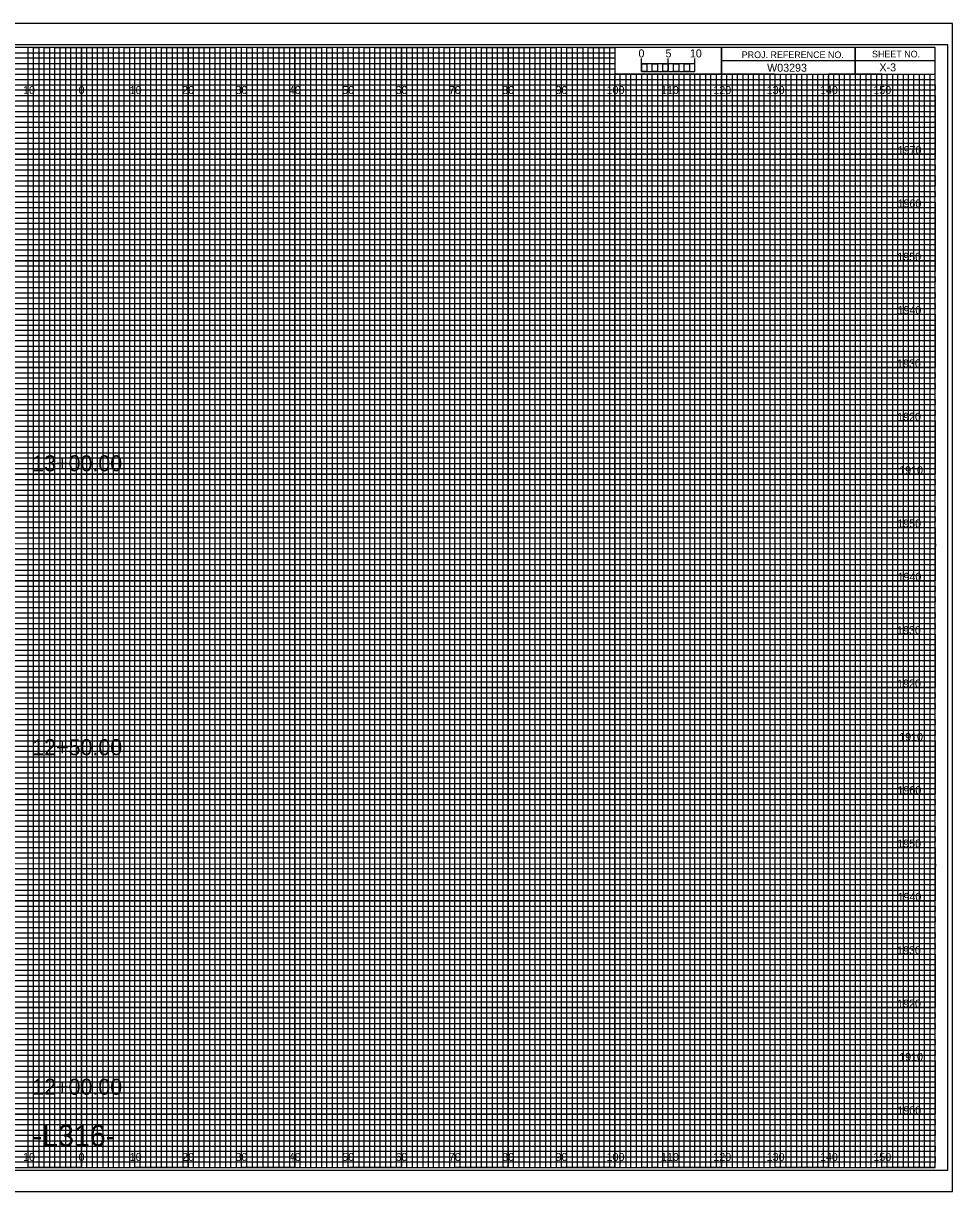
# Model space of a CAD drawing. Extents: x -13 to 323, y 215 to 434.
# Drawn here: x 149.1 to 323.3, y 215.5 to 434.5 of the extents above; entities that cross this region are included whole.
import ezdxf

# ---------------------------------------------------------------- set-up
doc = ezdxf.new("R2010")
doc.units = 0
for name, color, linetype in [('Exist Cross Section Cell', 7, 'Continuous'), ('Exist XS Center Line Elevation Label', 7, 'Continuous'), ('Exist XS Ground Line', 7, 'Continuous'), ('Prop CMT Concrete Ditch', 7, 'Continuous'), ('Prop XS Ditch Standard Text', 7, 'Continuous'), ('Prop XS Finish Grade Earthwork', 7, 'Continuous'), ('Prop XS Guardrail', 7, 'Continuous'), ('Prop XS Retaining Wall', 7, 'Continuous'), ('Prop XS SE Text', 7, 'Continuous'), ('Prop XS Side Slope Text', 7, 'Continuous'), ('Prop XS Subgrade Earthwork', 7, 'Continuous'), ('Prop XSC Text', 7, 'Continuous'), ('Scratch_Level_0', 7, 'Continuous'), ('Scratch_Level_5', 7, 'Continuous'), ('Scratch_Level_6', 7, 'Continuous'), ('Typical Guardrail CELL', 7, 'Continuous')]:
    doc.layers.add(name, color=color, linetype=linetype)

msp = doc.modelspace()

# ---------------------------------------------------------------- linework, layer by layer
at = {"layer": 'Exist Cross Section Cell'}
for points in [[(145, 220), (155, 220), (155, 430), (165, 430), (165, 220), (175, 220), (175, 430), (185, 430), (185, 220), (195, 220), (195, 430), (205, 430), (205, 220), (215, 220), (215, 430), (225, 430), (225, 220), (235, 220), (235, 430), (245, 430), (245, 220), (255, 220), (255, 430), (259.93, 430), (260, 430), (260, 425), (264.99, 425), (264.99, 220), (275, 220), (275, 425), (285, 425), (285, 220), (295, 220), (295, 425), (305, 425), (305, 220), (315, 220), (315, 425)], [(0, 425), (275, 425)], [(0, 405), (320, 405), (320, 415), (0, 415)], [(0, 385), (320, 385), (320, 395), (0, 395)], [(0, 365), (320, 365), (320, 375), (0, 375)], [(0, 345), (320, 345), (320, 355), (0, 355)], [(0, 325), (320, 325), (320, 335), (0, 335)], [(0, 305), (320, 305), (320, 315), (0, 315)], [(0, 285), (320, 285), (320, 295), (0, 295)], [(0, 265), (320, 265), (320, 275), (0, 275)], [(0, 245), (320, 245), (320, 255), (0, 255)], [(0, 225), (320, 225), (320, 235), (0, 235)]]:
    msp.add_lwpolyline(points, dxfattribs=at)
at = {"layer": 'Exist XS Center Line Elevation Label'}
for p, q in [((150, 430), (140, 430)), ((150, 220), (150, 430)), ((170, 430), (160, 430)), ((160, 430), (160, 220)), ((170, 220), (170, 430)), ((190, 430), (180, 430)), ((180, 430), (180, 220)), ((190, 220), (190, 430)), ((210, 430), (200, 430)), ((200, 430), (200, 220)), ((210, 220), (210, 430)), ((230, 430), (220, 430)), ((220, 430), (220, 220)), ((230, 220), (230, 430)), ((250, 430), (240, 430)), ((240, 430), (240, 220)), ((250, 220), (250, 430)), ((260, 430), (260, 220)), ((270, 220), (270, 425)), ((290, 425), (280, 425)), ((280, 425), (280, 220)), ((290, 220), (290, 425)), ((310, 425), (300, 425)), ((300, 425), (300, 220)), ((310, 220), (310, 425)), ((160, 220), (150, 220)), ((180, 220), (170, 220)), ((200, 220), (190, 220)), ((220, 220), (210, 220)), ((240, 220), (230, 220)), ((260, 220), (250, 220)), ((280, 220), (270, 220)), ((300, 220), (290, 220)), ((320, 220), (310, 220)), ((320, 220), (320, 220))]:
    msp.add_line(p, q, dxfattribs=at)
for points in [[(0, 420), (320, 420), (320, 410), (0, 410)], [(0, 400), (320, 400), (320, 390), (0, 390)], [(0, 380), (320, 380), (320, 370), (0, 370)], [(0, 360), (320, 360), (320, 350), (0, 350)], [(0, 340), (320, 340), (320, 330), (0, 330)], [(0, 320), (320, 320), (320, 310), (0, 310)], [(0, 300), (320, 300), (320, 290), (0, 290)], [(0, 280), (320, 280), (320, 270), (0, 270)], [(0, 260), (320, 260), (320, 250), (0, 250)], [(0, 240), (320, 240), (320, 230), (0, 230)]]:
    msp.add_lwpolyline(points, dxfattribs=at)
at = {"layer": 'Prop CMT Concrete Ditch'}
for p, q in [((265, 425.49), (265, 427.9)), ((265, 426.9), (265, 427.9)), ((270, 425.49), (270, 427.9)), ((275, 425.49), (275, 427.9)), ((275, 426.9), (275, 427.9))]:
    msp.add_line(p, q, dxfattribs=at)
for points in [[(275, 426.9), (265, 426.9), (265, 425.49), (275, 425.49)], [(265, 426.9), (266, 426.9), (266, 425.49), (265, 425.49)], [(267, 426.9), (268, 426.9), (268, 425.49), (267, 425.49)], [(269, 426.9), (270, 426.9), (270, 425.49), (269, 425.49)], [(271, 426.9), (272, 426.9), (272, 425.49), (271, 425.49)], [(273, 426.9), (274, 426.9), (274, 425.49), (273, 425.49)]]:
    msp.add_lwpolyline(points, close=True, dxfattribs=at)
at = {"layer": 'Prop XS Finish Grade Earthwork'}
for p, q in [((323.3, 434.5), (-13.4, 434.5)), ((-13.4, 215.5), (323.3, 215.5))]:
    msp.add_line(p, q, dxfattribs=at)
at = {"layer": 'Prop XS Retaining Wall'}
for p, q in [((267, 425), (266.01, 425)), ((266.01, 425), (266.01, 220)), ((267, 220), (267, 425)), ((269, 425), (268, 425)), ((268, 425), (268, 220)), ((269, 220), (269, 425)), ((266.01, 220), (265, 220)), ((268, 220), (267, 220))]:
    msp.add_line(p, q, dxfattribs=at)
for points in [[(150, 220), (151, 220), (151, 430), (152, 430), (152, 220)], [(152, 220), (153, 220), (153, 430), (154, 430), (154, 220)], [(155, 220), (156, 220), (156, 430), (157, 430), (157, 220)], [(157, 220), (158, 220), (158, 430), (159, 430), (159, 220)], [(160, 220), (161, 220), (161, 430), (162, 430), (162, 220)], [(162, 220), (163, 220), (163, 430), (164, 430), (164, 220)], [(165, 220), (166, 220), (166, 430), (167, 430), (167, 220)], [(167, 220), (168, 220), (168, 430), (169, 430), (169, 220)], [(170, 220), (171, 220), (171, 430), (172, 430), (172, 220)], [(172, 220), (173, 220), (173, 430), (174, 430), (174, 220)], [(175, 220), (176, 220), (176, 430), (177, 430), (177, 220)], [(177, 220), (178, 220), (178, 430), (179, 430), (179, 220)], [(180, 220), (181, 220), (181, 430), (182, 430), (182, 220)], [(182, 220), (183, 220), (183, 430), (184, 430), (184, 220)], [(185, 220), (186, 220), (186, 430), (187, 430), (187, 220)], [(187, 220), (188, 220), (188, 430), (189, 430), (189, 220)], [(190, 220), (191, 220), (191, 430), (192, 430), (192, 220)], [(192, 220), (193, 220), (193, 430), (194, 430), (194, 220)], [(195, 220), (196, 220), (196, 430), (197, 430), (197, 220)], [(197, 220), (198, 220), (198, 430), (199, 430), (199, 220)], [(200, 220), (201, 220), (201, 430), (202, 430), (202, 220)], [(202, 220), (203, 220), (203, 430), (204, 430), (204, 220)], [(205, 220), (206, 220), (206, 430), (207, 430), (207, 220)], [(207, 220), (208, 220), (208, 430), (209, 430), (209, 220)], [(210, 220), (211, 220), (211, 430), (212, 430), (212, 220)], [(212, 220), (213, 220), (213, 430), (214, 430), (214, 220)], [(215, 220), (216, 220), (216, 430), (217, 430), (217, 220)], [(217, 220), (218, 220), (218, 430), (219, 430), (219, 220)], [(220, 220), (221, 220), (221, 430), (222, 430), (222, 220)], [(222, 220), (223, 220), (223, 430), (224, 430), (224, 220)], [(225, 220), (226, 220), (226, 430), (227, 430), (227, 220)], [(227, 220), (228, 220), (228, 430), (229, 430), (229, 220)], [(230, 220), (231, 220), (231, 430), (232, 430), (232, 220)], [(232, 220), (233, 220), (233, 430), (234, 430), (234, 220)], [(235, 220), (236, 220), (236, 430), (237, 430), (237, 220)], [(237, 220), (238, 220), (238, 430), (239, 430), (239, 220)], [(240, 220), (241, 220), (241, 430), (242, 430), (242, 220)], [(242, 220), (243, 220), (243, 430), (244, 430), (244, 220)], [(245, 220), (246, 220), (246, 430), (247, 430), (247, 220)], [(247, 220), (248, 220), (248, 430), (249, 430), (249, 220)], [(250, 220), (251, 220), (251, 430), (252, 430), (252, 220)], [(252, 220), (253, 220), (253, 430), (254, 430), (254, 220)], [(255, 220), (256, 220), (256, 430), (257, 430), (257, 220)], [(257, 220), (258, 220), (258, 430), (259, 430), (259, 220)], [(260, 220), (261, 220), (261, 425), (262.02, 425), (262.02, 220)], [(262, 220), (263, 220), (263, 425), (263.99, 425), (263.99, 220)], [(270, 220), (270.98, 220), (270.98, 425), (272, 425), (272, 220)], [(272, 220), (273, 220), (273, 425), (274.05, 425), (274.05, 220)], [(275, 220), (276, 220), (276, 425), (277, 425), (277, 220)], [(277, 220), (278, 220), (278, 425), (279, 425), (279, 220)], [(280, 220), (281, 220), (281, 425), (282, 425), (282, 220)], [(282, 220), (283, 220), (283, 425), (284, 425), (284, 220)], [(285, 220), (286, 220), (286, 425), (287, 425), (287, 220)], [(287, 220), (288, 220), (288, 425), (289, 425), (289, 220)], [(290, 220), (291, 220), (291, 425), (292, 425), (292, 220)], [(292, 220), (293, 220), (293, 425), (294, 425), (294, 220)], [(295, 220), (296, 220), (296, 425), (297, 425), (297, 220)], [(297, 220), (298, 220), (298, 425), (299, 425), (299, 220)], [(300, 220), (301, 220), (301, 425), (302, 425), (302, 220)], [(302, 220), (303, 220), (303, 425), (304, 425), (304, 220)], [(305, 220), (306, 220), (306, 425), (307, 425), (307, 220)], [(307, 220), (308, 220), (308, 425), (309, 425), (309, 220)], [(310, 220), (311, 220), (311, 425), (312, 425), (312, 220)], [(312, 220), (313, 220), (313, 425), (314, 425), (314, 220)], [(315, 220), (316, 220), (316, 425), (317, 425), (317, 220)], [(317, 220), (318, 220), (318, 425), (319, 425), (319, 220)]]:
    msp.add_lwpolyline(points, dxfattribs=at)
at = {"layer": 'Prop XSC Text'}
for p, q in [((150, 220), (150, 430)), ((160, 220), (160, 430)), ((170, 220), (170, 430)), ((180, 220), (180, 430)), ((190, 220), (190, 430)), ((200, 220), (200, 430)), ((210, 220), (210, 430)), ((220, 220), (220, 430)), ((230, 220), (230, 430)), ((240, 220), (240, 430)), ((250, 220), (250, 430)), ((260, 220), (260, 424.69)), ((270, 220), (270, 424.69)), ((280, 220), (280, 424.69)), ((290, 220), (290, 424.69)), ((300, 220), (300, 424.69)), ((310, 220), (310, 424.69)), ((0, 420), (320, 420)), ((0, 410), (320, 410)), ((0, 400), (320, 400)), ((0, 390), (320, 390)), ((0, 380), (320, 380)), ((0, 370), (320, 370)), ((0, 360), (320, 360)), ((0, 350), (320, 350)), ((0, 340), (320, 340)), ((0, 330), (320, 330)), ((0, 320), (320, 320)), ((0, 310), (320, 310)), ((0, 300), (320, 300)), ((0, 290), (320, 290)), ((0, 280), (320, 280)), ((0, 270), (320, 270)), ((0, 260), (320, 260)), ((0, 250), (320, 250)), ((0, 240), (320, 240)), ((0, 230), (320, 230))]:
    msp.add_line(p, q, dxfattribs=at)
at = {"layer": 'Scratch_Level_0'}
msp.add_lwpolyline([(-10.8, 219.5), (322.4, 219.5), (322.4, 430.5), (-10.8, 430.5)], close=True, dxfattribs=at)
at = {"layer": 'Scratch_Level_5'}
for p, q in [((0, 429), (260, 429)), ((260, 427.98), (0, 427.98)), ((260, 429), (260, 427.98)), ((0, 427), (260, 427)), ((260, 425.89), (0, 425.89)), ((260, 427), (260, 425.89)), ((0, 424), (320, 424))]:
    msp.add_line(p, q, dxfattribs=at)
for points in [[(0, 423), (270, 423), (320, 423), (320, 422), (0, 422)], [(0, 421), (320, 421), (320, 419), (0, 419)], [(0, 418), (320, 418), (320, 417), (0, 416.98)], [(0, 416), (320, 416), (320, 414), (0, 414)], [(0, 413), (320, 413), (320, 412), (0, 412)], [(0, 411), (320, 411), (320, 409), (0, 409)], [(0, 408), (320, 408), (320, 407), (0, 407)], [(0, 406), (320, 406), (320, 404), (0, 404)], [(0, 403), (320, 403), (320, 402), (0, 402)], [(0, 401), (320, 401), (320, 399), (0, 399)], [(0, 398), (320, 398), (320, 397), (0, 397)], [(0, 396), (320, 396), (320, 393.95), (320, 393), (320, 392), (0, 392)], [(0, 394), (320, 394), (320, 393), (0, 393)], [(0, 391), (320, 391), (320, 389), (0, 389.03)], [(0, 389.03), (320, 389), (320, 388), (0, 388)], [(0, 387), (320, 387), (320, 386), (0, 386)], [(0, 384), (320, 384), (320, 383), (0, 383)], [(0, 382), (320, 382), (320, 381), (0, 381)], [(-0.07, 378.89), (320, 378.89), (320, 377.88), (-0.07, 377.88)], [(0, 377), (320, 377), (320, 376), (0, 376)], [(0, 374), (320, 374), (320, 373), (0, 373)], [(0, 372), (320, 372), (320, 371), (0, 371)], [(0, 369), (320, 369), (320, 368), (0, 368)], [(0, 367), (320, 367), (320, 366), (0, 366)], [(0, 364), (320, 364), (320, 363), (0, 363)], [(0, 362), (320, 362), (320, 361), (0, 361)], [(0, 359), (320, 359), (319.99, 357.98), (0, 358)], [(0, 357), (320, 357), (320, 356), (0, 356)], [(0, 354), (320, 354), (320, 353), (0, 353)], [(0, 352), (320, 352), (320, 351), (0, 351)], [(0, 349), (320, 349), (320, 348), (0, 348)], [(0, 347), (320, 347), (320, 346), (0, 346)], [(0, 344), (320, 344), (320, 343), (0, 343)], [(0, 342), (320, 342), (320, 341), (0, 341)], [(0, 339), (320, 339), (320, 338), (0, 338)], [(0, 336.99), (320.07, 336.91), (320, 336), (0, 336)], [(0, 334), (320, 334), (320, 333), (0, 333)], [(0, 332), (320, 332), (320, 331), (0, 331)], [(0, 329), (320, 329), (320, 328), (0, 328)], [(0, 327), (320, 327), (320, 326), (0, 326)], [(0, 324), (320, 324), (320, 323), (0, 323)], [(0, 322), (320, 322), (320, 321), (0, 321)], [(0, 319), (320, 319), (320, 318), (0, 318)], [(0, 317), (320, 317), (320, 316), (0, 316)], [(0, 314), (320, 314), (320, 313), (0, 313)], [(0, 312), (320, 312), (320, 311), (0, 311)], [(0, 309), (320, 309), (320, 308), (0, 308)], [(0, 307), (320, 307), (320, 306), (0, 306)], [(0, 304), (320, 304), (320, 303), (0, 303)], [(0, 302), (320, 302), (320, 301), (0, 301)], [(0, 299), (320, 299), (319.99, 297.98), (0, 298)], [(0, 297), (320, 297), (320, 296), (0, 296)], [(0, 294), (320, 294), (320, 293), (0, 293)], [(0, 292), (320, 292), (320, 291), (0, 291)], [(0, 289), (320, 289), (320, 288), (0, 288)], [(0, 287), (320, 287), (320, 286), (0, 286)], [(0, 284), (320, 284), (320, 283), (0, 283)], [(0, 282), (320, 282), (320, 281), (0, 281)], [(0, 279), (320, 279), (320, 278), (0, 278)], [(0, 276.99), (320.07, 276.91), (320, 276), (0, 276)], [(0, 274), (320, 274), (320, 273), (0, 273)], [(0, 272), (320, 272), (320, 271), (0, 271)], [(0, 269), (320, 269), (320, 268), (0, 268)], [(0, 267), (320, 267), (320, 266), (0, 266)], [(0, 264), (320, 264), (320, 263), (0, 263)], [(0, 262), (320, 262), (320, 261), (0, 261)], [(0, 259), (320, 259), (320, 258), (0, 258)], [(0, 257), (320, 257), (320, 256), (0, 256)], [(0, 254), (320, 254), (320, 253), (0, 253)], [(0, 252), (320, 252), (320, 251), (0, 251)], [(0, 249), (320, 249), (320, 248), (0, 248)], [(0, 247), (320, 247), (320, 246), (0, 246)], [(0, 244), (320, 244), (320, 243), (0, 243)], [(0, 242), (320, 242), (320, 241), (0, 241)], [(0, 239), (320, 239), (320, 238), (0, 238)], [(0, 237), (320, 237), (320, 236), (0, 236)], [(0, 234), (320, 234), (320, 233), (0, 233)], [(0, 232), (320, 232), (320, 231), (0, 231)], [(0, 229), (320, 229), (320, 228), (0, 228)], [(0, 227), (320, 227), (320, 226), (0, 226)], [(0, 224), (320, 224), (320, 223), (0, 223)], [(0, 222), (320, 222), (320, 221), (0, 221)]]:
    msp.add_lwpolyline(points, dxfattribs=at)
at = {"layer": 'Scratch_Level_6'}
for p, q in [((305, 430), (305, 425)), ((305, 425), (305, 430)), ((280, 427.5), (280, 425)), ((320, 427.49), (280, 427.49)), ((280, 425), (320, 425))]:
    msp.add_line(p, q, dxfattribs=at)
for points in [[(320, 430), (0, 430), (0, 220), (320, 220)], [(280, 430), (260, 430), (260, 425.03), (280, 425.03)], [(320, 430), (280, 430), (280, 425), (320, 425)]]:
    msp.add_lwpolyline(points, close=True, dxfattribs=at)
at = {"layer": 'Typical Guardrail CELL'}
msp.add_lwpolyline([(-13.4, 215.5), (323.3, 215.5), (323.3, 434.5), (-13.4, 434.5)], close=True, dxfattribs=at)

# ---------------------------------------------------------------- texts
at = {"layer": 'Exist XS Ground Line'}
for s, p in [('10', (149.04, 421.25)), ('0', (159.45, 421.25)), ('0', (159.45, 421.25)), ('10', (169.04, 421.25)), ('20', (178.86, 421.25)), ('30', (188.86, 421.25)), ('40', (198.86, 421.25)), ('50', (208.86, 421.25)), ('60', (218.86, 421.25)), ('70', (228.86, 421.25)), ('80', (238.86, 421.25)), ('90', (248.86, 421.25)), ('100', (258.44, 421.25)), ('110', (268.62, 421.25)), ('120', (278.44, 421.25)), ('130', (288.44, 421.25)), ('140', (298.44, 421.25)), ('150', (308.44, 421.25)), ('10', (149.04, 221.25)), ('0', (159.45, 221.25)), ('0', (159.45, 221.25)), ('10', (169.04, 221.25)), ('20', (178.86, 221.25)), ('30', (188.86, 221.25)), ('40', (198.86, 221.25)), ('50', (208.86, 221.25)), ('60', (218.86, 221.25)), ('70', (228.86, 221.25)), ('80', (238.86, 221.25)), ('90', (248.86, 221.25)), ('100', (258.44, 221.25)), ('110', (268.62, 221.25)), ('120', (278.44, 221.25)), ('130', (288.44, 221.25)), ('140', (298.44, 221.25)), ('150', (308.44, 221.25))]:
    msp.add_text(s, height=1.5, dxfattribs=at).set_placement(p)
at = {"layer": 'Prop CMT Concrete Ditch'}
msp.add_text('0', height=1.5, dxfattribs=at).set_placement((264.41, 428.12))
at = {"layer": 'Prop XS Ditch Standard Text'}
for s, p in [('W03293', (288.52, 425.43)), ('X-3', (309.57, 425.5))]:
    msp.add_text(s, height=1.5, dxfattribs=at).set_placement(p)
at = {"layer": 'Prop XS Guardrail'}
for s, p in [('1970', (313, 410)), ('1960', (312.97, 400)), ('1950', (312.92, 390)), ('1940', (312.97, 380)), ('1930', (312.89, 370)), ('1920', (312.9, 360)), ('1910', (313.28, 350)), ('1950', (312.92, 340)), ('1940', (312.97, 330)), ('1930', (312.89, 320)), ('1920', (312.9, 310)), ('1910', (313.28, 300)), ('1900', (312.95, 290)), ('1960', (312.97, 290)), ('1950', (312.92, 280)), ('1940', (312.97, 270)), ('1930', (312.89, 260)), ('1920', (312.9, 250)), ('1910', (313.28, 240)), ('1900', (312.95, 230))]:
    msp.add_text(s, height=1.5, dxfattribs=at).set_placement(p)
at = {"layer": 'Prop XS SE Text'}
for s, p in [('5', (269.47, 428.12)), ('10', (274.04, 428.12))]:
    msp.add_text(s, height=1.5, dxfattribs=at).set_placement(p)
at = {"layer": 'Prop XS Side Slope Text'}
for s, p in [('13+00.00', (150.77, 350.53)), ('12+50.00', (150.77, 297.31)), ('12+00.00', (150.77, 233.66))]:
    msp.add_text(s, height=3, dxfattribs=at).set_placement(p)
at = {"layer": 'Prop XS Subgrade Earthwork'}
msp.add_text('-L316-', height=4, dxfattribs=at).set_placement((150.84, 224))
at = {"layer": 'Scratch_Level_6'}
for s, p in [('PROJ. REFERENCE NO.', (283.77, 427.99)), ('SHEET NO.', (308.19, 428.12))]:
    msp.add_text(s, height=1.25, dxfattribs=at).set_placement(p)

doc.saveas('drawing.dxf')
